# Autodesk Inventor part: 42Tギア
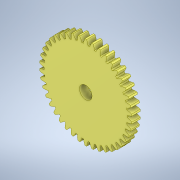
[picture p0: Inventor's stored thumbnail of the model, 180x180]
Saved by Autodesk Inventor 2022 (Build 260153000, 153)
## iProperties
CustomPartVersion: 1
Created: 2024-11
Part Number: 42Tギア
Material: Steel
Document SubType Name: Modeling
Designer: neo09
Categories: <?xml version="1.0" encoding="UTF-16"?> <MemberInstance><Categories><FamilyTemplate><FamilyTemplateParameter ValueType="xs:double" Id="1" ObjectReferenceKey="da
Density: 1 g/cm^3
Appearance: Steel
Author: neo09
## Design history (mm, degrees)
sketch "Sketch1"
  geometry: C1 r 11 at (0, 0)
  constraints: 1 centre point
  dimensions: "d0" = 22 diameter of C1 (= da_da)
extrude "Extrusion1" new body sketch "Sketch1" distance "d1" = 2 (= da_b); taper "d2" = 0 deg
workplane "Work Plane2"
sketch "Sketch2"
  geometry: C1 r 11 at (0, 0) reference; C2 r 10.5 at (0, 0)
  constraints: 1 centre point, 1 coincident
  dimensions: "d3" = 21 diameter of C2 (= da_d)
feature "ピッチ円直径" sketch "Sketch2" dims "d4" = 10, "d5" = 0
workplane "Work Plane8"
workplane "Work Plane9"
feature "平歯車" dims "da_b" = 2, "da_d" = 21, "da_aw" = 24.75, "da_da" = 22, "da_df" = 19.75, "da_dw" = 21, angle "da_beta" = 0 deg, "da_lefttooth" = 0, "da_righttooth" = 0
sketch "スケッチ3"
  geometry: C1 r 1.5 at (0, 0); 1 further point
  constraints: 1 centre point, 1 coincident
  dimensions: "d49" = 3 diameter of C1
extrude "押し出し2" cut sketch "スケッチ3" distance "d50" = 10; taper "d51" = 0 deg
body "Solid1"
body "Srf1"
other parameters: "d16" = 24.75 (= da_aw), "d17" = 0, "d34" = 0.748 (computed from da_z), "d39" = 0, "d41" = 0, "d43" = 24.75 (= da_aw), "d46" = 24.75 (= da_aw), "d47" = 0, "d48" = 0
